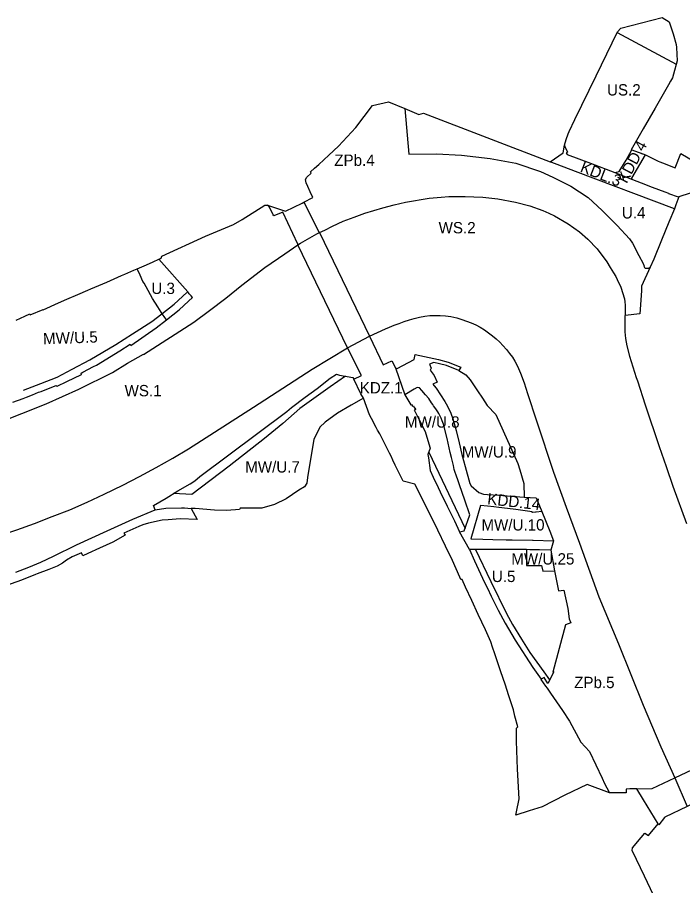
# Model space of a CAD drawing. Extents: x 7421697 to 7426767, y 5545731 to 5547485.
# Drawn here: x 7422926 to 7423631, y 5546361 to 5547280 of the extents above; entities that cross this region are included whole.
import ezdxf

# ---------------------------------------------------------------- set-up
doc = ezdxf.new("R2010")
doc.units = 0
for name, color, linetype in [('LIN_Linia Zabudowy Nieprzekraczalna', 7, 'Continuous'), ('LIN_linie rozgraniczające terenu WS', 7, 'Continuous'), ('LIN_linie_rozgraniczajace', 7, 'Continuous'), ('TXT_oznaczenia_przeznaczen', 7, 'Continuous')]:
    doc.layers.add(name, color=color, linetype=linetype)

msp = doc.modelspace()

# ---------------------------------------------------------------- linework, layer by layer
at = {"layer": 'LIN_Linia Zabudowy Nieprzekraczalna'}
for p, q in [((7423561.65, 5547264), (7423624.14, 5547230.16)), ((7423361.87, 5546819.52), (7423400.27, 5546738.69))]:
    msp.add_line(p, q, dxfattribs=at)
for points in [[(7422932.46, 5546885.15), (7422950.79, 5546892.36), (7422968.19, 5546899.01), (7422984.04, 5546907.22), (7423002.86, 5546917.12), (7423030.3, 5546933.5), (7423047.96, 5546944.94), (7423068.42, 5546957.7), (7423078.99, 5546965.86), (7423092.27, 5546976.2), (7423105.51, 5546988.7)], [(7423273.62, 5546899.98), (7423257.56, 5546888.67), (7423225.13, 5546865.68), (7423207.13, 5546849.85), (7423187.73, 5546833.85), (7423150.37, 5546804.85), (7423110.99, 5546774.86), (7423091.33, 5546775.63)], [(7423410.88, 5546717.18), (7423427.75, 5546682.42), (7423444.35, 5546648.8), (7423450.62, 5546637.03), (7423460, 5546621.43), (7423468.91, 5546607.57), (7423483.71, 5546586.83), (7423489.81, 5546578.34)]]:
    msp.add_lwpolyline(points, dxfattribs=at)
at = {"layer": 'LIN_linie rozgraniczające terenu WS'}
for p, q in [((7423275.73, 5546929.87), (7423298.93, 5546942.28)), ((7423622.42, 5546474.69), (7423635.75, 5546444.44))]:
    msp.add_line(p, q, dxfattribs=at)
msp.add_lwpolyline([(7423223.29, 5547039.1), (7423225.79, 5547040.83), (7423243.41, 5547050.55), (7423246.09, 5547051.91)], dxfattribs=at)
at = {"layer": 'LIN_linie_rozgraniczajace'}
for points in [[(7422924.7, 5546959.3), (7422933.83, 5546963.46), (7422939.19, 5546965.91), (7422939.69, 5546964.76), (7422953.17, 5546970.55), (7422953.3, 5546970.27), (7422969.62, 5546977.56), (7422978.38, 5546981.42), (7422989.98, 5546986.47), (7423000.72, 5546991.12), (7423003.69, 5546992.39), (7423020.7, 5546999.61), (7423036.36, 5547006.52), (7423039.87, 5547008.06), (7423049.4, 5547012.19), (7423052.97, 5547013.77), (7423062.77, 5547017.93), (7423070.01, 5547021.14), (7423075.7, 5547023.67), (7423078.48, 5547024.9), (7423079.14, 5547026.85), (7423125.29, 5547048.25), (7423154.92, 5547060.53), (7423164.09, 5547065.83), (7423188.22, 5547080.88), (7423190.85, 5547081.04), (7423210.16, 5547074.78), (7423227.76, 5547083.27), (7423229.66, 5547084.25), (7423238.98, 5547089.06), (7423236.26, 5547095.09), (7423233.68, 5547100.76), (7423231.95, 5547104.5), (7423231.26, 5547108.22), (7423232.6, 5547110.76), (7423237.38, 5547114.98), (7423236.44, 5547116.2), (7423240.91, 5547120.2), (7423245.38, 5547124.2), (7423255.87, 5547133.8), (7423266.36, 5547143.4), (7423275.53, 5547153.32), (7423284.69, 5547163.23), (7423302.11, 5547186.44), (7423319.05, 5547190.41), (7423336.4, 5547183.28), (7423351.36, 5547176.86), (7423356.12, 5547178.59), (7423490.57, 5547127.06), (7423504.36, 5547136.28), (7423505.73, 5547144.64), (7423507.59, 5547150.55), (7423509.46, 5547156.46), (7423510.49, 5547159.01), (7423516.58, 5547171.54), (7423539.24, 5547218.02), (7423561.9, 5547264.5), (7423565.46, 5547268.47), (7423609.03, 5547279.85), (7423616.54, 5547275.25), (7423620.67, 5547262.59), (7423624.01, 5547251.28), (7423624.49, 5547248.09), (7423625.09, 5547233.75), (7423621.34, 5547219.59), (7423620.11, 5547215.95), (7423618.09, 5547212.41), (7423615.81, 5547208.37), (7423601.77, 5547183.76), (7423589.11, 5547161.76), (7423576.46, 5547139.76), (7423577.08, 5547139.53), (7423591.65, 5547134.16), (7423600.72, 5547129.66), (7423604.92, 5547127.57), (7423606.58, 5547126.88), (7423609.6, 5547125.66), (7423622.86, 5547120.54), (7423629.11, 5547135.76), (7423642.9, 5547127.66)], [(7423336.4, 5547183.28), (7423340.9, 5547135.1), (7423369.99, 5547135.34), (7423396.58, 5547133.79), (7423426.8, 5547130.42), (7423454.15, 5547125.5), (7423480.17, 5547116.77), (7423493.48, 5547110.68), (7423512.25, 5547101.18), (7423530.72, 5547089.21), (7423545.66, 5547075.52), (7423561.48, 5547059.61), (7423574.62, 5547045.28), (7423577.8, 5547040.93), (7423584.46, 5547027.75), (7423588.97, 5547019.1), (7423590.09, 5547016.56), (7423589.62, 5547016.36), (7423590.57, 5547015.05), (7423591.31, 5547014.48), (7423592.84, 5547014.22), (7423594.9, 5547014.45), (7423596.56, 5547015.51)], [(7423505.73, 5547144.64), (7423506.13, 5547143.22), (7423508.71, 5547137.19), (7423507.57, 5547136.52), (7423508.47, 5547134.78)], [(7423558.86, 5547115.54), (7423563.78, 5547116.69), (7423570.9, 5547128.53), (7423577.08, 5547139.53)], [(7423622.16, 5547077.15), (7423517.34, 5547116.8), (7423490.57, 5547127.06)], [(7423508.47, 5547134.78), (7423533.13, 5547125.54), (7423558.86, 5547115.54), (7423562.4, 5547114.17), (7423577.65, 5547108.27), (7423586.95, 5547104.6), (7423598.64, 5547100.18), (7423612.02, 5547095.12), (7423615.88, 5547093.69), (7423615.81, 5547093.5), (7423626.03, 5547089.68), (7423626.09, 5547089.86), (7423626.9, 5547089.53)], [(7423577.65, 5547108.27), (7423577.4, 5547108.42), (7423577.21, 5547108.63), (7423577.08, 5547108.87), (7423577.03, 5547109.15), (7423577.05, 5547109.43), (7423577.15, 5547109.71), (7423591.65, 5547134.16)], [(7423246.09, 5547051.91), (7423251.62, 5547054.72), (7423259.84, 5547058.89), (7423271.21, 5547063.92), (7423282.73, 5547068.19), (7423294.24, 5547072.46), (7423313.25, 5547078.34), (7423325.26, 5547081.29), (7423337.27, 5547084.23), (7423362.45, 5547088.46), (7423374.93, 5547089.62), (7423383.04, 5547090.04), (7423400.27, 5547090.26), (7423409.65, 5547089.79), (7423419.02, 5547089.32), (7423434.97, 5547087.7), (7423453.83, 5547084.21), (7423469.02, 5547080.25), (7423482.87, 5547075.42), (7423489.04, 5547072.56), (7423495.2, 5547069.7), (7423509.58, 5547061.37), (7423521.6, 5547052.64), (7423530.43, 5547044.93), (7423540.16, 5547034.63), (7423550.53, 5547020.86), (7423554.14, 5547015.14), (7423557.76, 5547009.41), (7423560.11, 5547005.33), (7423561.64, 5547002.18), (7423565.32, 5546994.09), (7423569.34, 5546982.02), (7423569.73, 5546978.59), (7423570.11, 5546975.17), (7423569.9, 5546964.11)], [(7423638.68, 5547093.59), (7423626.96, 5547089.69), (7423623.74, 5547081.23), (7423622.16, 5547077.15), (7423616.37, 5547062.99), (7423608.37, 5547043.91), (7423600.18, 5547024), (7423596.56, 5547015.51), (7423587.45, 5546995.35), (7423587.43, 5546992.74), (7423587.27, 5546990.39), (7423585.42, 5546965.82), (7423569.9, 5546964.11), (7423569.61, 5546964.08), (7423569.77, 5546959.82), (7423569.6, 5546953.61), (7423569.73, 5546946.85), (7423570.45, 5546939.92), (7423571.8, 5546931.92), (7423574.61, 5546921.04), (7423581.65, 5546898.47), (7423582.92, 5546894.89), (7423591.31, 5546869.49), (7423605.97, 5546825.53), (7423613.31, 5546804.22), (7423620.53, 5546783.43), (7423634.85, 5546743.81)], [(7423207.37, 5547073.66), (7423197.64, 5547069.77), (7423196.95, 5547070.92), (7423193.07, 5547078.79), (7423192.19, 5547080.22), (7423190.85, 5547081.04)], [(7423229.66, 5547084.25), (7423245.92, 5547052.25), (7423245.93, 5547052.24), (7423298.93, 5546942.28), (7423313.59, 5546911.85)], [(7423290.48, 5546900.5), (7423275.73, 5546929.87), (7423275.63, 5546930.06), (7423223.29, 5547039.1), (7423223.07, 5547039.55), (7423207.37, 5547073.66)], [(7422917.18, 5546855.08), (7422930.57, 5546860.54), (7422956.59, 5546870.76), (7422991.27, 5546886.26), (7423026.63, 5546903.82), (7423042.57, 5546913.58), (7423059.46, 5546923.19), (7423059.65, 5546922.86), (7423113.08, 5546957.22), (7423129.62, 5546969.5), (7423146.71, 5546982.7), (7423163.75, 5546996.45), (7423188.19, 5547015.17), (7423209.37, 5547029.51), (7423223.29, 5547039.1)], [(7422921.17, 5546872.55), (7422931.97, 5546876.36), (7422935.69, 5546877.83), (7422942.09, 5546880.38), (7422948.5, 5546882.92), (7422951.09, 5546883.91), (7422953.68, 5546884.9), (7422967.07, 5546890.02), (7422967.99, 5546889.37), (7422978.55, 5546894.24), (7422993.98, 5546901.77), (7422993.56, 5546903.19), (7422995.18, 5546904.05), (7423006.77, 5546910.14), (7423009.79, 5546911.73), (7423034.53, 5546926.7), (7423045.4, 5546933.75), (7423046.22, 5546932.41), (7423073.16, 5546951.25), (7423083.9, 5546959.54), (7423097.49, 5546970.12), (7423107.16, 5546979.25), (7423111.41, 5546983.26), (7423109.96, 5546984.94), (7423107.94, 5546987.27), (7423106.42, 5546989.23), (7423075.7, 5547023.67)], [(7423083.9, 5546959.54), (7423081.4, 5546963.09), (7423079.38, 5546965.95), (7423078.17, 5546967.68), (7423074.86, 5546973.35), (7423069.32, 5546982.28), (7423062.37, 5546994.47), (7423060.18, 5546998.32), (7423059.03, 5547000.36), (7423056, 5547007.05), (7423052.97, 5547013.77)], [(7423298.93, 5546942.28), (7423316.18, 5546950.24), (7423320.25, 5546951.85), (7423325.34, 5546953.88), (7423330.51, 5546955.81), (7423335.98, 5546957.7), (7423341.33, 5546959.46), (7423346.54, 5546961.03), (7423352.05, 5546962.41), (7423357.59, 5546963.45), (7423363.11, 5546964.09), (7423368.47, 5546964.34), (7423374.02, 5546964.27), (7423379.71, 5546963.83), (7423385.13, 5546963.02), (7423391.59, 5546961.68), (7423396.96, 5546960.07), (7423401.98, 5546958.22), (7423406.86, 5546956.27), (7423411.62, 5546954.17), (7423416.33, 5546951.76), (7423420.96, 5546948.94), (7423425.29, 5546945.88), (7423429.42, 5546942.79), (7423433.32, 5546939.49), (7423437.1, 5546935.99), (7423440.52, 5546932.35), (7423444.13, 5546928.27), (7423447.39, 5546924.13), (7423450.44, 5546919.93), (7423453.04, 5546915.77), (7423455.86, 5546910.53), (7423459.16, 5546903.22), (7423462.89, 5546892.98), (7423466.56, 5546881.67), (7423475.87, 5546852.72), (7423494.08, 5546798.42), (7423507.35, 5546761.15), (7423521.46, 5546723.32), (7423542.21, 5546666.27), (7423562.81, 5546616.43), (7423588.95, 5546551.76), (7423607.93, 5546507.53), (7423622.42, 5546474.69)], [(7422906.35, 5546730.92), (7422925.3, 5546737.28), (7422944.22, 5546744.12), (7422962.85, 5546751.36), (7422981.56, 5546758.6), (7422999.8, 5546766.68), (7423018.04, 5546775), (7423037.74, 5546784.62), (7423055.52, 5546793.71), (7423073.17, 5546803.13), (7423090.57, 5546813), (7423107.42, 5546822.96), (7423176.11, 5546867.28), (7423238.37, 5546907.25), (7423275.73, 5546929.87)], [(7423313.59, 5546911.85), (7423322.81, 5546916.36), (7423326.47, 5546908.69), (7423336.6, 5546880.06), (7423342.91, 5546869.61), (7423343.58, 5546870.01), (7423344.48, 5546868.07), (7423345.59, 5546868.57), (7423346.63, 5546866.01), (7423347.56, 5546866.43), (7423347.8, 5546864.67), (7423346.28, 5546864.03), (7423347.03, 5546862.86), (7423349.52, 5546858.06), (7423358.06, 5546841.55), (7423362.1, 5546828.44), (7423363.44, 5546823.77), (7423360.97, 5546817.08), (7423361.51, 5546813.43), (7423363.27, 5546800.09), (7423366.67, 5546792.99), (7423371.74, 5546782.12), (7423374.06, 5546777.45), (7423381.31, 5546762.49), (7423388.97, 5546746.89), (7423394.35, 5546735.26)], [(7423326.47, 5546908.69), (7423328.39, 5546908.19), (7423346.32, 5546917.62), (7423347.38, 5546922.96), (7423372.18, 5546917.46), (7423382.31, 5546914.66), (7423395.84, 5546909.6), (7423393.89, 5546906.05), (7423380.67, 5546911.37), (7423373.32, 5546912.96), (7423367.21, 5546914.28), (7423362.64, 5546912.68), (7423364.4, 5546908.54), (7423363.4, 5546906.48), (7423367.69, 5546900.84), (7423370.77, 5546893.62), (7423366.3, 5546891.61), (7423367.75, 5546889.77), (7423369.64, 5546887.13), (7423379.07, 5546873.04), (7423381.79, 5546868.35), (7423385.15, 5546860.76), (7423387.4, 5546854.64), (7423390.98, 5546842.32), (7423394.09, 5546829.44), (7423397.01, 5546817.19), (7423400.29, 5546804.22), (7423405.53, 5546786.18), (7423406.77, 5546783.95), (7423414.92, 5546776.8), (7423419.98, 5546774.95), (7423423.95, 5546774.69), (7423436.25, 5546773.9), (7423449.16, 5546773.08), (7423453.37, 5546772.81), (7423454.87, 5546772.49), (7423458.42, 5546772.25), (7423462.88, 5546771.94), (7423475.65, 5546771.16), (7423481.51, 5546756.63), (7423475.63, 5546755.97), (7423474.97, 5546755.9), (7423471.96, 5546755.56), (7423471.49, 5546755.51), (7423471.45, 5546756.44), (7423454.16, 5546758.71), (7423445.31, 5546759.75), (7423436.12, 5546760.83), (7423430.67, 5546761.47), (7423424.07, 5546762.24), (7423416.66, 5546763.11)], [(7423393.89, 5546906.05), (7423401.14, 5546901.26), (7423405.8, 5546896.01), (7423413.62, 5546884.27), (7423418.65, 5546876.59), (7423423.68, 5546868.91), (7423433.09, 5546859.26), (7423456.33, 5546807.62), (7423458.4, 5546800.75), (7423462.67, 5546786.27), (7423462.88, 5546771.94)], [(7423071.96, 5546758.37), (7423070.26, 5546763.06), (7423083.51, 5546770.93), (7423096.07, 5546778.48), (7423108.92, 5546786.06), (7423113.88, 5546789.29), (7423119.22, 5546793.79), (7423211.38, 5546862.57), (7423216.5, 5546866.63), (7423230.89, 5546877.76), (7423243.65, 5546886.89), (7423257.53, 5546897.8), (7423264.14, 5546901.99), (7423267.42, 5546901.14), (7423281.39, 5546898.54), (7423282.51, 5546896.96)], [(7423292.58, 5546876.57), (7423290.03, 5546881.44), (7423282.51, 5546896.96), (7423290.48, 5546900.5)], [(7423400.26, 5546768.76), (7423394.47, 5546785.04), (7423392.71, 5546790.1), (7423391.28, 5546794.21), (7423389.56, 5546799.11), (7423388.81, 5546801.26), (7423387.93, 5546805.34), (7423387.02, 5546809.6), (7423385.97, 5546813.74), (7423384.62, 5546819.08), (7423381.33, 5546833.96), (7423377.54, 5546849.16), (7423376.23, 5546852.81), (7423374.95, 5546855.45), (7423374.26, 5546856.88), (7423372.48, 5546860.54), (7423371.33, 5546862.32), (7423369.44, 5546865.24), (7423367.05, 5546868.62), (7423366.08, 5546870.06), (7423364.93, 5546871.77), (7423361.81, 5546876.39), (7423358.5, 5546880.24), (7423354.51, 5546884.89), (7423352.06, 5546887.73), (7423349.61, 5546888.07), (7423346.38, 5546886.03), (7423336.6, 5546880.06)], [(7423606.78, 5546336.34), (7423590.53, 5546370.45), (7423582.01, 5546388.09), (7423577.42, 5546397.75), (7423577.62, 5546400.44), (7423586.91, 5546411.37), (7423590.93, 5546416.22), (7423594.66, 5546413.68), (7423605.01, 5546426.05), (7423589.44, 5546451.54), (7423582.34, 5546463.05), (7423576.51, 5546462.92), (7423574.86, 5546462.89), (7423571.08, 5546462.8), (7423571.13, 5546458.84), (7423553.2, 5546458.74), (7423529.88, 5546467.68), (7423506.14, 5546456.25), (7423482.12, 5546444.07), (7423468.33, 5546439.76), (7423454.25, 5546435.34), (7423454.88, 5546438.66), (7423457.51, 5546452.48), (7423455.98, 5546483.76), (7423454.75, 5546513.47), (7423454.71, 5546523.18), (7423454.69, 5546527.27), (7423456.39, 5546528.54), (7423453.06, 5546540.16), (7423451.52, 5546546.75), (7423446.81, 5546561.48), (7423442.71, 5546573.77), (7423438.13, 5546586.88), (7423431.92, 5546605.91), (7423429.5, 5546612.99), (7423427.72, 5546618.76), (7423421.94, 5546631.52), (7423414.23, 5546647.71), (7423407.57, 5546662.31), (7423400.91, 5546676.61), (7423397.12, 5546684.67), (7423395.86, 5546684.78), (7423392.42, 5546692.88), (7423385.46, 5546707.88), (7423383.48, 5546712.01), (7423367.53, 5546745.08), (7423347.01, 5546785.7), (7423334.88, 5546788.63), (7423326.23, 5546805.84), (7423323.79, 5546811.2), (7423321.98, 5546815.12), (7423320.27, 5546818.61), (7423317.54, 5546824), (7423312.73, 5546833.22), (7423309.87, 5546838.77), (7423307.6, 5546842.95), (7423306.11, 5546845.6), (7423301.21, 5546855.13), (7423299.24, 5546858.94), (7423292.58, 5546876.57), (7423290.16, 5546875.19), (7423279.74, 5546869.21), (7423265.15, 5546860.71), (7423252.19, 5546851.24), (7423246.58, 5546845.87), (7423244.95, 5546842.81), (7423242.69, 5546838.08), (7423239.96, 5546833.07), (7423238.02, 5546820.58), (7423237.34, 5546815.96), (7423236.24, 5546810.05), (7423233.23, 5546792.78), (7423232.7, 5546786.65), (7423230.08, 5546782.82), (7423224.21, 5546779.33), (7423210.65, 5546770.01), (7423198.43, 5546764.03), (7423184.96, 5546760.16), (7423172.08, 5546760.35), (7423161.96, 5546760.29), (7423161.49, 5546758.95), (7423157.24, 5546758.57), (7423152.22, 5546758.1), (7423147.95, 5546757.73), (7423134.7, 5546758.2), (7423114.49, 5546759.84), (7423110, 5546759.93), (7423116.57, 5546748.25), (7423098.63, 5546748.82), (7423085.73, 5546747.99), (7423079.51, 5546747.66), (7423065.05, 5546744.25), (7423058.92, 5546742.6), (7423054.69, 5546740.72), (7423038.89, 5546733.83), (7423040.12, 5546731.59), (7423027.15, 5546724.2), (7423012.92, 5546717.72), (7423000.48, 5546712.12), (7422995.21, 5546709.7), (7422993.98, 5546712.83), (7422983.86, 5546708.75), (7422978.12, 5546705.31), (7422973.81, 5546702.14), (7422968.2, 5546698.93), (7422959.43, 5546695.29), (7422947.1, 5546690.58), (7422945.25, 5546689.84), (7422930.31, 5546683.88), (7422907.12, 5546675.71)], [(7423399.34, 5546736.06), (7423405.44, 5546753.28), (7423400.26, 5546768.76)], [(7422924.37, 5546692.51), (7422938.15, 5546697.79), (7422950.72, 5546703.06), (7422964.37, 5546709.39), (7422988.46, 5546721.57), (7423020.98, 5546736.32), (7423048.18, 5546748.59), (7423071.96, 5546758.37), (7423083.24, 5546760.1), (7423100, 5546760.61), (7423102.95, 5546760.53), (7423110, 5546759.93)], [(7423416.66, 5546763.11), (7423406.45, 5546727.68)], [(7423481.51, 5546756.63), (7423490.14, 5546735.72), (7423494.17, 5546725.55)], [(7423394.35, 5546735.26), (7423399.34, 5546736.06)], [(7423406.45, 5546727.68), (7423419.28, 5546727.25), (7423429.79, 5546727.02), (7423443.95, 5546726.7), (7423450.15, 5546726.56), (7423471.72, 5546726.44), (7423472.34, 5546726.41), (7423494.17, 5546725.55), (7423491.13, 5546715.71), (7423479.11, 5546715.95), (7423473.95, 5546716.08), (7423468.96, 5546716.21), (7423465.29, 5546716.3), (7423462.17, 5546716.37), (7423459.07, 5546716.44), (7423445.15, 5546716.43), (7423426.87, 5546716.59), (7423425.62, 5546716.62), (7423417.68, 5546716.5), (7423415.86, 5546716.49), (7423413.66, 5546716.48), (7423408.63, 5546716.45), (7423404.93, 5546716.31), (7423394.35, 5546735.26)], [(7423404.93, 5546716.31), (7423410.16, 5546704.28), (7423421.02, 5546681.44), (7423423.95, 5546675.53), (7423428.12, 5546666.88), (7423435.33, 5546652.27), (7423442.72, 5546638.45), (7423453.28, 5546620.41), (7423472.27, 5546591.69), (7423480.98, 5546579.31), (7423480.55, 5546578.98), (7423483.1, 5546575.41), (7423485.65, 5546571.83), (7423487.27, 5546569.61), (7423490.94, 5546564.44), (7423503.53, 5546545.99), (7423510.92, 5546534.77), (7423522.97, 5546512.57), (7423532.16, 5546502.52), (7423545.44, 5546474.47), (7423548, 5546468.86), (7423553.16, 5546459.53), (7423553.2, 5546458.74)], [(7423465.29, 5546716.3), (7423465.53, 5546699.57), (7423481.28, 5546699.5), (7423482.75, 5546693.58), (7423495.21, 5546693.9)], [(7423491.13, 5546715.71), (7423495.21, 5546693.9), (7423499.17, 5546672.67), (7423504.92, 5546673.29), (7423509.21, 5546654.06), (7423510.58, 5546643.22), (7423512.23, 5546638.85), (7423506.92, 5546636.6), (7423493.4, 5546586.65), (7423494.26, 5546586.8), (7423487.91, 5546574.75), (7423484, 5546581.09), (7423480.98, 5546579.31)], [(7423831.68, 5546528.39), (7423816.64, 5546525.52), (7423814.27, 5546524.88), (7423813.21, 5546524.74), (7423803.14, 5546521.92), (7423798.35, 5546520.43), (7423789.29, 5546517.31), (7423783.24, 5546515.06), (7423783.89, 5546511.73), (7423771.68, 5546505.64), (7423770.23, 5546509.11), (7423766.46, 5546507.34), (7423759.56, 5546502.45), (7423737.86, 5546492.89), (7423635.75, 5546444.44), (7423611.99, 5546433.22)], [(7423598.61, 5546463.4), (7423622.42, 5546474.69), (7423672.63, 5546498.5), (7423676.52, 5546500.25)], [(7423582.34, 5546463.05), (7423598.61, 5546463.4)], [(7423611.99, 5546433.22), (7423611.53, 5546432.67), (7423605.61, 5546424.87), (7423605.01, 5546426.05)]]:
    msp.add_lwpolyline(points, dxfattribs=at)

# ---------------------------------------------------------------- texts
at = {"layer": 'TXT_oznaczenia_przeznaczen'}
for s, p in [('US.2', (7423550.76, 5547197.11)), ('ZPb.4', (7423261.77, 5547122.62)), ('U.4', (7423566.48, 5547066.93)), ('WS.2', (7423372.3, 5547051.17)), ('U.3', (7423067.92, 5546986.95)), ('WS.1', (7423039.57, 5546878.65)), ('KDZ.1', (7423288.76, 5546881.68)), ('MW/U.8', (7423336.58, 5546845.46)), ('MW/U.9', (7423396.85, 5546813.85)), ('MW/U.7', (7423167.37, 5546797.9)), ('MW/U.10', (7423417.66, 5546736.56)), ('MW/U.25', (7423449.31, 5546700.53)), ('U.5', (7423428.75, 5546682)), ('ZPb.5', (7423515.92, 5546569.69))]:
    msp.add_text(s, height=12, dxfattribs=at).set_placement(p)
for s, rotation, p in [('KDD.4', 62.07392, (7423571.53, 5547103.21)), ('KDL.3', 338.57575, (7423521.44, 5547116.73)), ('MW/U.5', 1.96361, (7422953.37, 5546933.66)), ('KDD.14', 353.4738, (7423423.47, 5546764.45))]:
    msp.add_text(s, height=12, rotation=rotation, dxfattribs=at).set_placement(p)

doc.saveas('drawing.dxf')
